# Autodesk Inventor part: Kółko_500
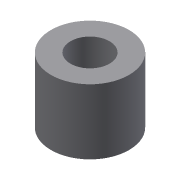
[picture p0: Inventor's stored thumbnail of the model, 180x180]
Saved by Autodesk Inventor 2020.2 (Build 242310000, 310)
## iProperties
Created: 2014-11
Part Number: Kółko_500
Material: Ogólny
Document SubType Name: Modeling
Designer: F.Stasiak
Density: 1 g/cm^3
Appearance: Domyślna
Catalog Web Link: www.expertbooks.pl
Manager: www.cadconsulting.pl
Company: Fabian Stasiak CAD Consulting
Author: F.Stasiak
Subject: Zbiór ćwiczeń. Autodesk Inventor 2020. Kurs Professional
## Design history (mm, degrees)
sketch "Szkic1"
  geometry: C1 r 30 at (0, 0); 1 further point
  constraints: 1 centre point, 1 coincident
  dimensions: "d0" = 60 diameter of C1
extrude "Wyciągnięcie proste1" new body sketch "Szkic1" distance "d1" = 50; taper "d2" = 0 deg
sketch "Szkic2"
  geometry: C1 r 15 at (0, 0); 1 further point
  constraints: 1 centre point, 1 coincident
  dimensions: "d3" = 30 diameter of C1
extrude "Wyciągnięcie proste2" cut sketch "Szkic2" extent not by distance; stored distance "d4" = 50; taper "d5" = 0 deg
node "Bryła1"
